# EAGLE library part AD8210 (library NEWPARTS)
High Voltage, Bidirectional Current Shunt Monitor
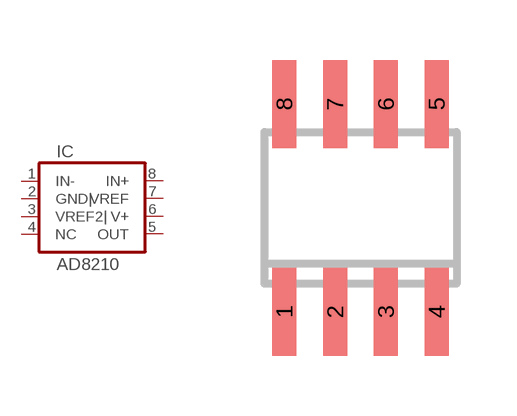
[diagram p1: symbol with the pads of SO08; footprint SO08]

Designator prefix IC

## AD8210D  [SO08]
1  IN-  in
2  GND|  in
3  VREF2|  in
4  NC  pwr
5  OUT  pwr
6  V+  in
7  VREF  in
8  IN+  out

## Footprint SO08 (pad centres in mm)
Small Outline Package 8 NS Package M08A
smd 0.6 x 2.2: 1 -1.905,-2.6; 2 -0.635,-2.6; 3 0.635,-2.6; 4 1.905,-2.6; 5 1.905,2.6; 6 0.635,2.6; 7 -0.635,2.6; 8 -1.905,2.6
